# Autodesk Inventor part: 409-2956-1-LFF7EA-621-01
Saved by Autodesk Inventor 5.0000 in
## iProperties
Created: 2010-06
Part Number: 409-2956-1-LFF7EA-621-01
Cost Center: 0 lbmass
Material: A36 STEEL PLATE
Document SubType Name: Sheet Metal
Designer: S. Boerckel
Authority: 0 in^3
Mass: 8052.98 g
Surface Area: 761.54 cm^2
Volume: 1024.55 cm^3
Density: 7.86 g/cm^3
Flat Pattern Width: 15.24 cm
Flat Pattern Length: 15.24 cm
Flat Pattern Area: 232.258 cm^2
Sheet Metal Rule: 1-3/4" THK
Sheet Metal Width: 10.0000 in
Sheet Metal Length: 50.0000 in^2
Description: STAINER FOOT PLATE
User Status: BURN
SaveDate: 2008-01-15
SaveTime: 10:24
FileName: Sheet Metal
Wide: =<Flat Pattern Width>cm
Length: =<Flat Pattern Length>cm
Thickness: 1.7500 in
SMR: =<Sheet Metal Rule> - <Material>
Author: S. Boerckel
Revision Number: 0
Subject: DEMIN WATER FORWARDING PUMP SKID-7EA
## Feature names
1. Hole2
2. Plate1
